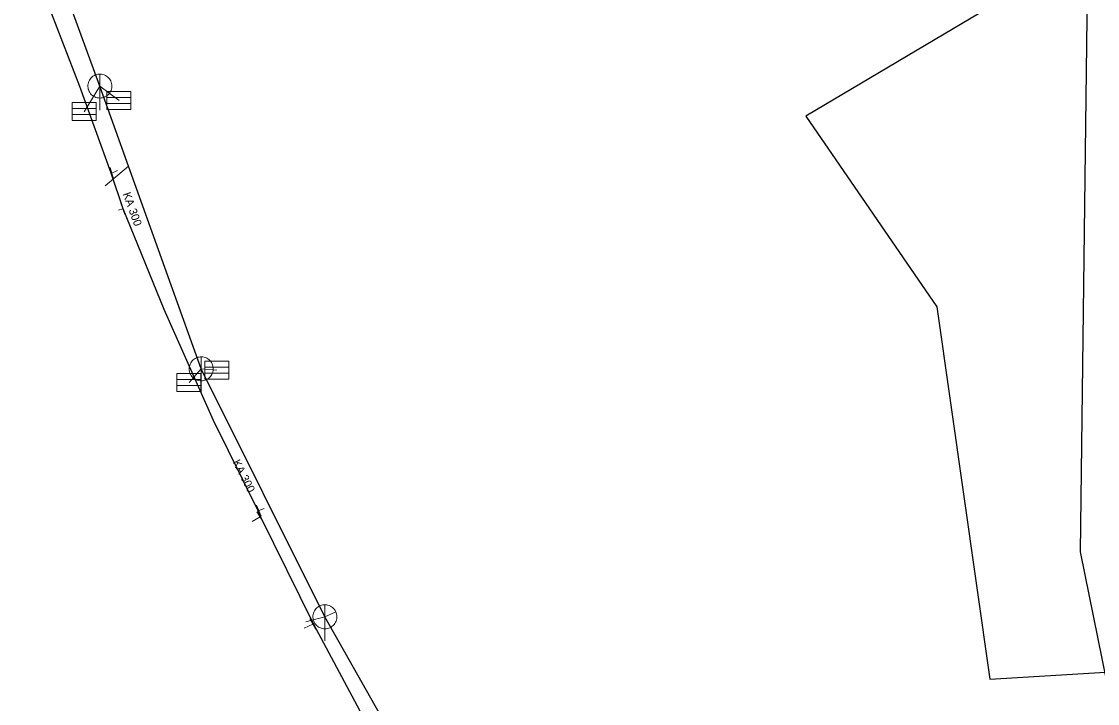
# Model space of a CAD drawing. Extents: x -688432 to -687974, y -973332 to -972704.
# Drawn here: x -688238.6 to -688148.9, y -972987.1 to -972930.3 of the extents above; entities that cross this region are included whole.
import ezdxf
from ezdxf.enums import TextEntityAlignment as Align

# ---------------------------------------------------------------- set-up
doc = ezdxf.new("R2010")
doc.units = 0
doc.header["$LTSCALE"] = 0.27
for name, color, linetype, lineweight in [('1', 7, 'Continuous', 25), ('11', 7, 'Continuous', 13), ('13', 7, 'Continuous', 13), ('14', 7, 'Continuous', 25), ('17', 7, 'Continuous', 25), ('22', 7, 'Continuous', 13), ('34', 7, 'Continuous', 13)]:
    doc.layers.add(name, color=color, linetype=linetype, lineweight=lineweight)

msp = doc.modelspace()

# ---------------------------------------------------------------- linework, layer by layer
at = {"layer": '1'}
msp.add_lwpolyline([(-688157.895, -972985.064), (-688131.748, -972983.489), (-688134.952, -972934.372), (-688122, -972934.52), (-688122.986, -972921.456), (-688135.938, -972921.308), (-688137.958, -972895.554), (-688157.714, -972894.909), (-688157.93, -972929.126), (-688173.215, -972938.189), (-688162.29, -972954.057)], close=True, dxfattribs=at)
at = {"layer": '11'}
for p, q in [((-688233.35, -972937.82), (-688232.039, -972935.68)), ((-688230.44, -972936.889), (-688232.039, -972935.68)), ((-688231.594, -972944.002), (-688229.648, -972942.349)), ((-688224.609, -972960.379), (-688223.6, -972959.23)), ((-688222.283, -972959.335), (-688223.6, -972959.23)), ((-688212.421, -972979.48), (-688213.289, -972979.879)), ((-688214.872, -972980.285), (-688213.289, -972979.879))]:
    msp.add_line(p, q, dxfattribs=at)
at = {"layer": '13'}
for p, q in [((-688231.041, -972942.935), (-688230.559, -972942.719)), ((-688230.135, -972945.915), (-688230.5, -972946.02)), ((-688218.791, -972971.04), (-688218.35, -972970.85)), ((-688218.691, -972971.555), (-688219.35, -972971.949)), ((-688214.295, -972980.494), (-688215.02, -972980.82))]:
    msp.add_line(p, q, dxfattribs=at)
at = {"layer": '14', "lineweight": 13}
for p, q in [((-688231.09, -972942.949), (-688231.041, -972942.935)), ((-688230.09, -972945.899), (-688230.135, -972945.915)), ((-688218.84, -972971.059), (-688218.791, -972971.04)), ((-688218.649, -972971.53), (-688218.691, -972971.555)), ((-688214.25, -972980.469), (-688214.295, -972980.494))]:
    msp.add_line(p, q, dxfattribs=at)
at = {"layer": '14'}
for points in [[(-688232.039, -972935.68), (-688234.738, -972928.309), (-688238.57, -972919.1)], [(-688223.6, -972959.23), (-688229.648, -972942.349), (-688232.039, -972935.68)], [(-688191.489, -973018.5), (-688193.675, -973014.629), (-688199.167, -973004.908), (-688202.881, -972998.296), (-688213.289, -972979.879), (-688223.6, -972959.23)]]:
    msp.add_lwpolyline(points, dxfattribs=at)
at = {"layer": '17'}
for points in [[(-688123.609, -972815.609), (-688135.91, -972839.761), (-688146.524, -972867.704), (-688149.164, -972878.87), (-688150.368, -972974.473), (-688134.778, -973051.136), (-688125.903, -973068.701), (-688203.651, -973132.27), (-688148.612, -973199.748), (-688078.631, -973291.807), (-688049.631, -973331.642)], [(-688167.42, -973053.719), (-688175.149, -973043.51), (-688175.68, -973042.93), (-688189.18, -973023.62), (-688194.239, -973015.879), (-688201.127, -973004.614), (-688201.64, -973003.76), (-688208.85, -972990.539), (-688214.25, -972980.469), (-688218.649, -972971.53), (-688218.84, -972971.059), (-688222.559, -972963.52), (-688226.68, -972954.28), (-688230.09, -972945.899), (-688231.09, -972942.949), (-688233.719, -972935.719), (-688236.539, -972928.36), (-688237.969, -972924.559)]]:
    msp.add_lwpolyline(points, dxfattribs=at)
at = {"layer": '22'}
for p, q in [((-688232.04, -972937.68), (-688232.039, -972934.68)), ((-688231.451, -972936.632), (-688229.451, -972936.632)), ((-688231.451, -972937.132), (-688229.451, -972937.132)), ((-688234.361, -972937.563), (-688232.361, -972937.563)), ((-688234.361, -972938.063), (-688232.361, -972938.063)), ((-688223.6, -972961.23), (-688223.599, -972958.23)), ((-688223.294, -972959.078), (-688221.294, -972959.078)), ((-688223.294, -972959.578), (-688221.294, -972959.578)), ((-688225.62, -972960.122), (-688223.62, -972960.122)), ((-688225.62, -972960.622), (-688223.62, -972960.622)), ((-688213.289, -972981.879), (-688213.288, -972978.879))]:
    msp.add_line(p, q, dxfattribs=at)
for points in [[(-688231.04, -972935.68), (-688231.045, -972935.571), (-688231.063, -972935.463), (-688231.093, -972935.357), (-688231.133, -972935.256), (-688231.185, -972935.159), (-688231.247, -972935.069), (-688231.319, -972934.986), (-688231.399, -972934.912), (-688231.487, -972934.846), (-688231.581, -972934.791), (-688231.681, -972934.746), (-688231.786, -972934.713), (-688231.893, -972934.691), (-688232.002, -972934.681), (-688232.112, -972934.683), (-688232.22, -972934.697), (-688232.327, -972934.722), (-688232.43, -972934.759), (-688232.528, -972934.808), (-688232.62, -972934.866), (-688232.706, -972934.935), (-688232.783, -972935.012), (-688232.852, -972935.098), (-688232.911, -972935.19), (-688232.959, -972935.288), (-688232.996, -972935.391), (-688233.022, -972935.498), (-688233.036, -972935.606), (-688233.039, -972935.716), (-688233.029, -972935.825), (-688233.008, -972935.932), (-688232.974, -972936.036), (-688232.93, -972936.136), (-688232.875, -972936.231), (-688232.809, -972936.319), (-688232.735, -972936.399), (-688232.652, -972936.471), (-688232.562, -972936.533), (-688232.466, -972936.585), (-688232.364, -972936.626), (-688232.259, -972936.656), (-688232.151, -972936.674), (-688232.041, -972936.68), (-688231.932, -972936.674), (-688231.824, -972936.656), (-688231.719, -972936.627), (-688231.617, -972936.586), (-688231.52, -972936.534), (-688231.43, -972936.472), (-688231.347, -972936.401), (-688231.272, -972936.321), (-688231.207, -972936.233), (-688231.151, -972936.139), (-688231.107, -972936.039), (-688231.073, -972935.935), (-688231.051, -972935.827), (-688231.041, -972935.718)], [(-688231.451, -972936.132), (-688229.451, -972936.132), (-688229.451, -972937.632), (-688231.451, -972937.632)], [(-688234.361, -972937.063), (-688232.361, -972937.063), (-688232.361, -972938.563), (-688234.361, -972938.563)], [(-688222.6, -972959.23), (-688222.605, -972959.121), (-688222.623, -972959.013), (-688222.653, -972958.907), (-688222.693, -972958.806), (-688222.745, -972958.709), (-688222.807, -972958.619), (-688222.879, -972958.536), (-688222.959, -972958.462), (-688223.047, -972958.396), (-688223.141, -972958.341), (-688223.241, -972958.296), (-688223.346, -972958.263), (-688223.453, -972958.241), (-688223.562, -972958.231), (-688223.672, -972958.233), (-688223.78, -972958.247), (-688223.887, -972958.272), (-688223.99, -972958.309), (-688224.088, -972958.358), (-688224.18, -972958.416), (-688224.266, -972958.485), (-688224.343, -972958.562), (-688224.412, -972958.648), (-688224.471, -972958.74), (-688224.519, -972958.838), (-688224.556, -972958.941), (-688224.582, -972959.048), (-688224.596, -972959.156), (-688224.599, -972959.266), (-688224.589, -972959.375), (-688224.568, -972959.482), (-688224.534, -972959.586), (-688224.49, -972959.686), (-688224.435, -972959.781), (-688224.369, -972959.869), (-688224.295, -972959.949), (-688224.212, -972960.021), (-688224.122, -972960.083), (-688224.026, -972960.135), (-688223.924, -972960.176), (-688223.819, -972960.206), (-688223.711, -972960.224), (-688223.601, -972960.23), (-688223.492, -972960.224), (-688223.384, -972960.206), (-688223.279, -972960.177), (-688223.177, -972960.136), (-688223.08, -972960.084), (-688222.99, -972960.022), (-688222.907, -972959.951), (-688222.832, -972959.871), (-688222.767, -972959.783), (-688222.711, -972959.689), (-688222.667, -972959.589), (-688222.633, -972959.485), (-688222.611, -972959.377), (-688222.601, -972959.268)], [(-688223.294, -972958.578), (-688221.294, -972958.578), (-688221.294, -972960.078), (-688223.294, -972960.078)], [(-688225.62, -972959.622), (-688223.62, -972959.622), (-688223.62, -972961.122), (-688225.62, -972961.122)], [(-688212.289, -972979.879), (-688212.294, -972979.77), (-688212.312, -972979.662), (-688212.342, -972979.556), (-688212.382, -972979.455), (-688212.434, -972979.358), (-688212.496, -972979.268), (-688212.568, -972979.185), (-688212.648, -972979.111), (-688212.736, -972979.045), (-688212.83, -972978.99), (-688212.93, -972978.945), (-688213.035, -972978.912), (-688213.142, -972978.89), (-688213.251, -972978.88), (-688213.361, -972978.882), (-688213.469, -972978.896), (-688213.576, -972978.921), (-688213.679, -972978.958), (-688213.777, -972979.007), (-688213.869, -972979.065), (-688213.955, -972979.134), (-688214.032, -972979.211), (-688214.101, -972979.297), (-688214.16, -972979.389), (-688214.208, -972979.487), (-688214.245, -972979.59), (-688214.271, -972979.697), (-688214.285, -972979.805), (-688214.288, -972979.915), (-688214.278, -972980.024), (-688214.257, -972980.131), (-688214.223, -972980.235), (-688214.179, -972980.335), (-688214.124, -972980.43), (-688214.058, -972980.518), (-688213.984, -972980.598), (-688213.901, -972980.67), (-688213.811, -972980.732), (-688213.715, -972980.784), (-688213.613, -972980.825), (-688213.508, -972980.855), (-688213.4, -972980.873), (-688213.29, -972980.879), (-688213.181, -972980.873), (-688213.073, -972980.855), (-688212.968, -972980.826), (-688212.866, -972980.785), (-688212.769, -972980.733), (-688212.679, -972980.671), (-688212.596, -972980.6), (-688212.521, -972980.52), (-688212.456, -972980.432), (-688212.4, -972980.338), (-688212.356, -972980.238), (-688212.322, -972980.134), (-688212.3, -972980.026), (-688212.29, -972979.917)]]:
    msp.add_lwpolyline(points, close=True, dxfattribs=at)
at = {"layer": '34'}
for p, q in [((-688231.183, -972942.455), (-688230.899, -972943.414)), ((-688229.968, -972946.386), (-688230.3, -972945.443)), ((-688218.979, -972970.576), (-688218.603, -972971.503)), ((-688218.423, -972971.977), (-688218.957, -972971.132)), ((-688214.052, -972980.931), (-688214.536, -972980.056))]:
    msp.add_line(p, q, dxfattribs=at)

# ---------------------------------------------------------------- texts
at = {"layer": '1'}
for rotation, p in [(290, (-688229.6423, -972946.0387)), (290, (-688229.6423, -972946.0387)), (290, (-688229.6423, -972946.0387)), (290, (-688229.6423, -972946.0387)), (290, (-688229.6423, -972946.0387)), (297, (-688220.3323, -972968.3005)), (297, (-688220.3323, -972968.3005)), (297, (-688220.3323, -972968.3005)), (297, (-688220.3323, -972968.3005)), (297, (-688220.3323, -972968.3005))]:
    msp.add_text('KA 300', height=0.6667, rotation=rotation, dxfattribs=at).set_placement(p, align=Align.CENTER)

doc.saveas('drawing.dxf')
